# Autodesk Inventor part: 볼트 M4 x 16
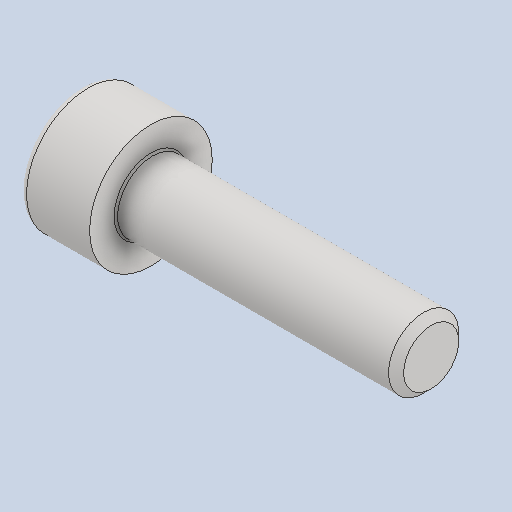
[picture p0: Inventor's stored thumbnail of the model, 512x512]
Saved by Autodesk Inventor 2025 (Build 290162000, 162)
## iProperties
Created: 2024-07
Part Number: 볼트 M4 x 16
Material: 스테인리스강
Description: 6각 소켓 머리 캡 나사
Document SubType Name: Modeling
Designer: parkm
Density: 8.08 g/cm^3
Appearance: 기본값
Author: jhkim
Sending System: Autodesk Inventor 2025
Preprocessor: ST-DEVELOPER v20
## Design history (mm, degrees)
feature "Solid1"
node "솔리드1"
